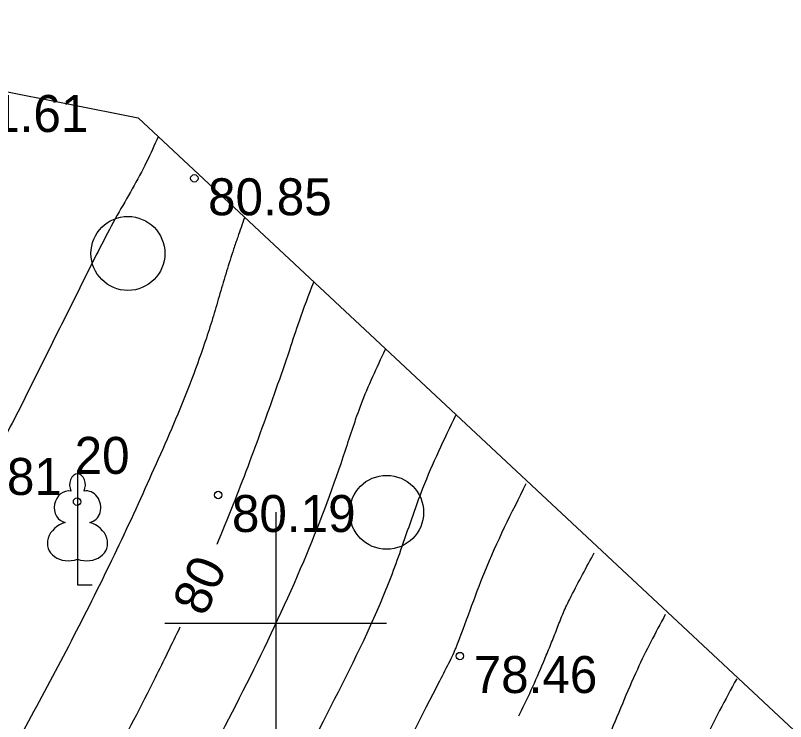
# Model space of a CAD drawing. Extents: x 576692 to 577659, y 273254 to 273799.
# Drawn here: x 577246.48 to 577256.9, y 273448.67 to 273458.22 of the extents above; entities that cross this region are included whole.
import ezdxf

# ---------------------------------------------------------------- set-up
doc = ezdxf.new("R2010")
doc.units = 0
for name, color, linetype in [('APGR_SARK_####_####_#', 7, 'Continuous'), ('CELI_TAKA_####_####_#', 7, 'Continuous'), ('CKOM_ELEM_####_####_#', 7, 'Continuous'), ('GEOD_ELEM_####_TKST_#', 7, 'Continuous'), ('GEOD_SITP_####_TKST_#', 7, 'Continuous'), ('HIDT_REZV_####_TKST_#', 7, 'Continuous'), ('LKAN_ELEM_PAST_TKST_#', 7, 'Continuous'), ('RELJ_ELEM_####_####_#', 7, 'Continuous'), ('RELJ_HORZ_PAMT_####_#', 7, 'Continuous')]:
    doc.layers.add(name, color=color, linetype=linetype)

msp = doc.modelspace()

# ---------------------------------------------------------------- linework, layer by layer
at = {"layer": 'CELI_TAKA_####_####_#'}
msp.add_lwpolyline([(577175.353, 273468.597), (577186.541, 273460.401), (577209.755, 273452.336), (577213.035, 273463.823), (577248.138, 273456.832), (577262.689, 273443.249), (577269.097, 273442.704), (577268.898, 273436.394), (577301.349, 273426.359), (577308.434, 273412.519), (577319.001, 273409.126), (577359.322, 273426.883), (577382.525, 273495.967), (577376.088, 273498.638), (577384.502, 273518.904), (577411.715, 273507.613), (577405.2, 273487.348), (577452.189, 273444.346)], dxfattribs=at)
at = {"layer": 'CKOM_ELEM_####_####_#'}
for p, q in [((577250, 273451.5), (577250, 273450)), ((577248.5, 273450), (577250, 273450)), ((577250, 273450), (577250, 273448.5)), ((577250, 273450), (577251.5, 273450))]:
    msp.add_line(p, q, dxfattribs=at)
at = {"layer": 'GEOD_ELEM_####_TKST_#'}
for points in [[(577249.206, 273451.069), (577249.423, 273451.6), (577249.818, 273452.644), (577250.188, 273453.697), (577250.32, 273454.09), (577250.513, 273454.614)], [(577253.288, 273448.75), (577253.325, 273448.823), (577253.659, 273449.567), (577253.742, 273449.768), (577253.821, 273449.971), (577253.903, 273450.172), (577253.997, 273450.367), (577254.309, 273450.952)], [(577237.31, 273435.982), (577238.817, 273437.25), (577239.916, 273438.213), (577240.915, 273439.193), (577241.896, 273440.146), (577242.448, 273440.573), (577242.738, 273440.771), (577243.018, 273440.982), (577243.168, 273441.126), (577243.387, 273441.392), (577243.6, 273441.662), (577244.014, 273442.212), (577244.813, 273443.324), (577245.577, 273444.46), (577246.317, 273445.612), (577247.158, 273447.012), (577248.372, 273449.267), (577248.708, 273449.952)]]:
    msp.add_spline(points, degree=3, dxfattribs=at)
at = {"layer": 'GEOD_SITP_####_TKST_#'}
for points in [[(577248.408, 273456.577), (577248.253, 273456.237), (577247.855, 273455.516), (577247.448, 273454.733), (577247.054, 273453.943), (577246.659, 273453.152), (577246.247, 273452.369), (577245.6, 273451.5), (577245.025, 273450.923), (577244.44, 273450.36), (577243.845, 273449.809), (577243.24, 273449.268), (577242.777, 273448.869), (577242.311, 273448.475), (577241.846, 273448.079), (577241.389, 273447.674), (577240.023, 273446.358), (577237.898, 273444.133), (577237.886, 273444.12), (577237.867, 273444.101), (577237.22, 273443.515), (577236.558, 273442.945), (577235.895, 273442.377), (577235.243, 273441.796), (577234.519, 273441.099), (577234.099, 273440.643), (577233.697, 273440.171), (577233.293, 273439.701), (577232.869, 273439.249), (577232.846, 273439.227), (577232.842, 273439.223), (577232.036, 273438.569), (577231.595, 273438.287), (577231.144, 273438.032)], [(577249.575, 273455.482), (577249.485, 273455.222), (577249.43, 273455.059), (577249.335, 273454.759), (577249.245, 273454.458), (577249.156, 273454.156), (577249.061, 273453.856), (577248.645, 273452.759), (577248.411, 273452.221), (577248.17, 273451.684), (577247.645, 273450.575), (577247.089, 273449.485), (577246.507, 273448.407), (577245.905, 273447.334), (577245.65, 273446.907), (577245.501, 273446.71), (577245.326, 273446.536), (577245.066, 273446.334), (577244.799, 273446.142), (577244.049, 273445.616), (577243.294, 273445.097), (577242.541, 273444.574), (577241.8, 273444.033), (577241.093, 273443.367), (577240.53, 273442.726), (577239.984, 273442.072), (577239.437, 273441.419), (577238.871, 273440.784), (577238.748, 273440.658), (577235.26, 273437.435), (577234.551, 273436.828), (577233.901, 273436.399), (577233.501, 273436.181), (577233.097, 273435.975), (577232.27, 273435.604)], [(577238.465, 273432.992), (577239.2, 273433.717), (577239.418, 273433.965), (577239.734, 273434.366), (577240.902, 273436.063), (577241.25, 273436.591), (577242.601, 273438.403), (577243.641, 273439.669), (577243.837, 273439.918), (577245.953, 273442.834), (577247.249, 273444.846), (577248.916, 273447.851), (577250.42, 273450.936), (577250.943, 273452.34), (577251.155, 273452.959), (577251.484, 273453.704)], [(577240.276, 273432.78), (577241.672, 273434.839), (577242.23, 273435.702), (577244.06, 273438.12), (577244.676, 273438.923), (577245.026, 273439.413), (577245.536, 273440.129), (577246.905, 273442.085), (577247.577, 273443.071), (577248.242, 273444.064), (577248.782, 273444.993), (577250.646, 273448.677), (577251.416, 273450.272), (577251.693, 273450.991), (577251.991, 273451.827), (577252.437, 273452.815)], [(577241.457, 273432.508), (577242.849, 273434.507), (577243.117, 273434.896), (577243.954, 273436.038), (577245.451, 273438.052), (577246.3, 273439.24), (577247.541, 273440.978), (577249.165, 273443.524), (577252.22, 273449.224), (577252.357, 273449.493), (577252.413, 273449.609), (577252.434, 273449.66), (577252.826, 273450.695), (577253.389, 273451.89)], [(577255.267, 273450.117), (577254.891, 273449.377), (577254.49, 273448.441), (577254.279, 273447.983), (577251.699, 273443.039), (577251.314, 273442.346), (577251.137, 273442.074), (577249.369, 273439.639), (577248.836, 273438.894), (577247.007, 273436.303), (577245.652, 273434.495), (577245.256, 273433.946), (577244.78, 273433.126)], [(577256.236, 273449.251), (577255.786, 273448.386), (577255.32, 273447.317), (577255.237, 273447.14), (577254.2, 273445.187), (577252.393, 273441.99), (577251.595, 273440.737), (577249.946, 273438.448), (577249.632, 273438.021), (577248.523, 273436.46), (577247.792, 273435.421), (577247.248, 273434.738), (577246.457, 273433.709), (577246.042, 273433.007)]]:
    msp.add_spline(points, degree=3, dxfattribs=at)
at = {"layer": 'LKAN_ELEM_PAST_TKST_#'}
for p, q in [((577247.318, 273450.867), (577247.318, 273450.52)), ((577247.318, 273450.52), (577247.518, 273450.52))]:
    msp.add_line(p, q, dxfattribs=at)
for points in [[(577247.318, 273452.02), (577247.318, 273450.867)], [(577247.408, 273451.788), (577247.407, 273451.789)]]:
    msp.add_lwpolyline(points, dxfattribs=at)
for centre in [(577248, 273455), (577251.5, 273451.5)]:
    msp.add_circle(centre, 0.5, dxfattribs=at)
for centre, major_axis, ratio, start_param, end_param in [((577247.318, 273451.87), (0, -0.15), 0.707107, 3.14537, 5.287485), ((577247.318, 273451.87), (0, -0.15), 0.707107, 0.995701, 3.137816), ((577247.19, 273451.575), (-0.039, -0.212), 0.861323, 3.141593, 6.283185), ((577247.446, 273451.575), (0.039, -0.212), 0.861323, 0, 3.141593), ((577247.228, 273451.113), (0.307, 0.095), 0.814445, 1.570796, 4.752015), ((577247.408, 273451.113), (-0.307, 0.095), 0.814445, 1.531171, 4.712389)]:
    msp.add_ellipse(centre, major_axis=major_axis, ratio=ratio, start_param=start_param, end_param=end_param, dxfattribs=at)
at = {"layer": 'RELJ_ELEM_####_####_#'}
for centre in [(577248.898, 273456.016), (577249.221, 273451.734), (577247.312, 273451.644), (577252.491, 273449.557)]:
    msp.add_circle(centre, 0.05, dxfattribs=at)

# ---------------------------------------------------------------- texts
at = {"layer": 'APGR_SARK_####_####_#'}
msp.add_text(' 20', height=0.5, dxfattribs=at).set_placement((577247.093, 273452.02))
at = {"layer": 'HIDT_REZV_####_TKST_#'}
for s, p in [(' 81.61', (577245.606, 273456.642)), (' 80.85', (577248.898, 273455.516)), (' 80.81', (577245.248, 273451.735)), (' 80.19', (577249.221, 273451.234)), (' 78.46', (577252.491, 273449.057))]:
    msp.add_text(s, height=0.5, dxfattribs=at).set_placement(p)
at = {"layer": 'RELJ_HORZ_PAMT_####_#'}
msp.add_text('80', height=0.5, rotation=66.0408, dxfattribs=at).set_placement((577249.044, 273450.076))

doc.saveas('drawing.dxf')
